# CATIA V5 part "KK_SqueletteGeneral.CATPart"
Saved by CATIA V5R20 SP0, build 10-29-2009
Part number: Squelette_general
Publications: "Longueur panneau pivotant", "hauteur panneau pivotant", "Plan reference", "Point.1", "Point.2", "Point.3", "Point.4", "Point.5", "Point.6", "Plan reference 2", "Point.7", "Point.8", "Point.9", "Point.10", "Point.13", "Point.12", "Point.11", "Point.14", "Point.15", "Longueur corps d'amortisseur", "Longueur corps de verin", "Point.16", "Point.17", "Point.18", "Longueur corps de verin de relevage", "Point.19", "Longueur tige amortisseur", "Point.20", "Point.21", "Point.22", "Point.23", "Point.24", "Point.25", "Point.26", "Point.27", "Droite.3", "Plan reference contre fiche", "Point.34", "Longueur tige verin de relevage", "Longueur contre fiche superieure", "Longueur tige verin", "Point.35", "Point.36", "Point.37", "Point.38"
Bounding box of the stored display mesh (mm): x -2496 to 480, y -288 to 1632, z -3072 to 600
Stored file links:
  G:\Khaled_CFAO_2011\ST2M\ST2M_GR2\aboulegue\Khaled\CAD_thinkMOTION\KK_SqueletteGeneral.CATPart
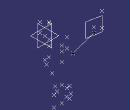
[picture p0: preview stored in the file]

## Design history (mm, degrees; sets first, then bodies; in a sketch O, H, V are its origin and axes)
Parameters
  `Longueur panneau pivotant` = 1056 mm
  `hauteur panneau pivotant` = 1280 mm
  `Longueur tige verin` = 1280 mm
  `Longueur corps d'amortisseur` = 1780 mm
  `Longueur corps de verin` = 1280 mm
  `Longueur corps de verin de relevage` = 1184 mm
  `Longueur tige amortisseur` = 2208 mm
  `Longueur tige verin de relevage` = 960 mm
  `Longueur contre fiche superieure` = 1280 mm
Set1 "References"
  Plane1 "Plan reference": type Offset, RefPlane yz-plane, Offset 0
  Plane2 "Plan reference 2": type Offset, RefPlane zx-plane, Offset 0
  Point1: (0, 0, 0)
  Point2: (0, 1056 {= `Longueur panneau pivotant`}, 0)
  Point3: (0, 0, -1280 {= -`hauteur panneau pivotant`})
  Point4: (0, 1056 {= `Longueur panneau pivotant`}, -320 {= -`hauteur panneau pivotant` /4})
  Point5: (0, 1056 {= `Longueur panneau pivotant`}, -3072 {= (-`hauteur panneau pivotant` /4)-544mm-`Longueur tige amortisseur`})
  Point6: (0, 768 {= `Longueur panneau pivotant` -288mm}, -2592 {= (-`hauteur panneau pivotant` /4)-544mm-`Longueur tige amortisseur` +480mm})
  Point7: (160, 640 {= `Longueur panneau pivotant` -416mm}, -1600 {= (-`hauteur panneau pivotant` /4)-1280mm})
  Point8: (0, 1376 {= `Longueur panneau pivotant` +320mm}, -2100 {= (-`hauteur panneau pivotant` /4)-`Longueur corps d'amortisseur`})
  Point9: (0, 1344 {= `Longueur panneau pivotant` +288mm}, -2592 {= (-`hauteur panneau pivotant` /4)-544mm-`Longueur tige amortisseur` +480mm})
  Point10 "Point.10": (-256, 0, -1280 {= -`hauteur panneau pivotant`})
  Point11 "Point.12": (-1984 {= -1984mm*(`Longueur contre fiche superieure` /1280mm)}, 1056 {= `Longueur panneau pivotant` *(`Longueur contre fiche superieure` /1280mm)}, -320 {= (- `hauteur panneau pivotant` /4)*(`Longueur contre fiche superieure` /1280mm)})
  Point12 "Point.11": (-288, 0, 512)
  Point13 "Point.13": type OnCurve, Support Line4, Length 1280 {= `Longueur corps de verin`}
  Point14 "Point.14": (0, 1056 {= `Longueur panneau pivotant`}, -2100 {= -(`hauteur panneau pivotant` /4)-`Longueur corps d'amortisseur`})
  Line1: type PtPt, FirstPoint Point11, SecondPoint Point7
  Point15 "Point.15": type OnCurve, Support Line1, Length 1280 {= `Longueur contre fiche superieure`}
  Point16 "Point.16": (-1984, 1056 {= `Longueur panneau pivotant`}, 0)
  Point17 "Point.17": (0, 1056 {= `Longueur panneau pivotant`}, -864 {= -(`hauteur panneau pivotant` /4)-544mm})
  Point18 "Point.18": (-2496 {= -2496mm*(`Longueur contre fiche superieure` /1280mm)}, 1056 {= `Longueur panneau pivotant` *(`Longueur contre fiche superieure` /1280mm)}, -320 {= (-`hauteur panneau pivotant` /4)*(`Longueur contre fiche superieure` /1280mm)})
  Line2: type PtPt, FirstPoint Point12, SecondPoint Point10
  Point19 "Point.19": type OnCurve, Support Line2, Length 1184 {= `Longueur corps de verin de relevage`}
  Point20 "Point.20": type OnCurve, Support Line4, Length 1280 {= `Longueur tige verin`}
  Point21 "Point.21": type OnCurve, Support Line2, Length 960 {= `Longueur tige verin de relevage`}
  Point22 "Point.22": (0, -288, 0)
  Point23 "Point.23": (0, 1376 {= `Longueur panneau pivotant` +320mm}, 0)
  Point24 "Point.24": (-288, 0, 600)
  Point25 "Point.25": (0, -288, 600)
  Point26 "Point.26": (0, 1376 {= `Longueur panneau pivotant` +320mm}, 600)
  Point27 "Point.27": (-2496 {= -2496mm*(`Longueur contre fiche superieure` /1280mm)}, 1056 {= `Longueur panneau pivotant`}, 600 {= 600mm*(`Longueur contre fiche superieure` /1280mm)})
  Line3: type PtPt, FirstPoint Point11, SecondPoint Point15
  Plane3 "Plan reference contre fiche": type 1Line1Pt, RefPoint Point16, Line Line1
  Point28: (0, 1632 {= `Longueur panneau pivotant` +576mm}, -2292 {= (-`hauteur panneau pivotant` /4)-`Longueur corps d'amortisseur`-192mm})
  Line4: type PtPt, FirstPoint Point6, SecondPoint Point3
  Point29: (480, 1056 {= `Longueur panneau pivotant`}, -3072 {= (-`hauteur panneau pivotant` /4)-544mm-`Longueur tige amortisseur`})
  Point30: (-480, 1056 {= `Longueur panneau pivotant`}, -3072 {= (-`hauteur panneau pivotant` /4)-544mm-`Longueur tige amortisseur`})
  Point31: (480, 1056 {= `Longueur panneau pivotant`}, -2400 {= (-`hauteur panneau pivotant` /4)-544mm-`Longueur tige amortisseur` +672mm})
  Point32: (-480, 1056 {= `Longueur panneau pivotant`}, -2400 {= (-`hauteur panneau pivotant` /4)-544mm-`Longueur tige amortisseur` +672mm})
Body1 (main body)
